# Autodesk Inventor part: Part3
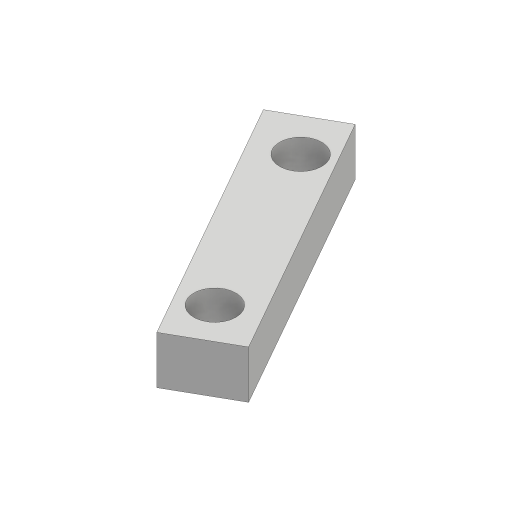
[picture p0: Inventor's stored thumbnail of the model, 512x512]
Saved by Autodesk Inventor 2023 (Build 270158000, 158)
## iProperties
Created: 2017-05
Part Number: Part3
Material: Generic
Document SubType Name: Modeling
Designer: CADCIM 00
Density: 1 g/cm^3
Appearance: Default
Author: CADCIM 00
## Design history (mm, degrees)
sketch "Sketch1"
  geometry: L1 (-30.267, 40.394)-(-1.138, -10.969); L2 (-1.138, -10.969)-(11.085, -4.037); L3 (11.085, -4.037)-(-18.043, 47.326); L4 (-18.043, 47.326)-(-30.267, 40.394); C1 r 4.406 at (-18.304, 36.224) reference; C2 r 4.406 at (0, 0) reference; 1 further point
  constraints: 8 end point, 2 parallel, 1 perpendicular
extrude "Extrusion1" new body sketch "Sketch1" distance "d0" = 10; taper "d1" = 0 deg
body "Solid1"
node "Reference1"
node "Reference2"
